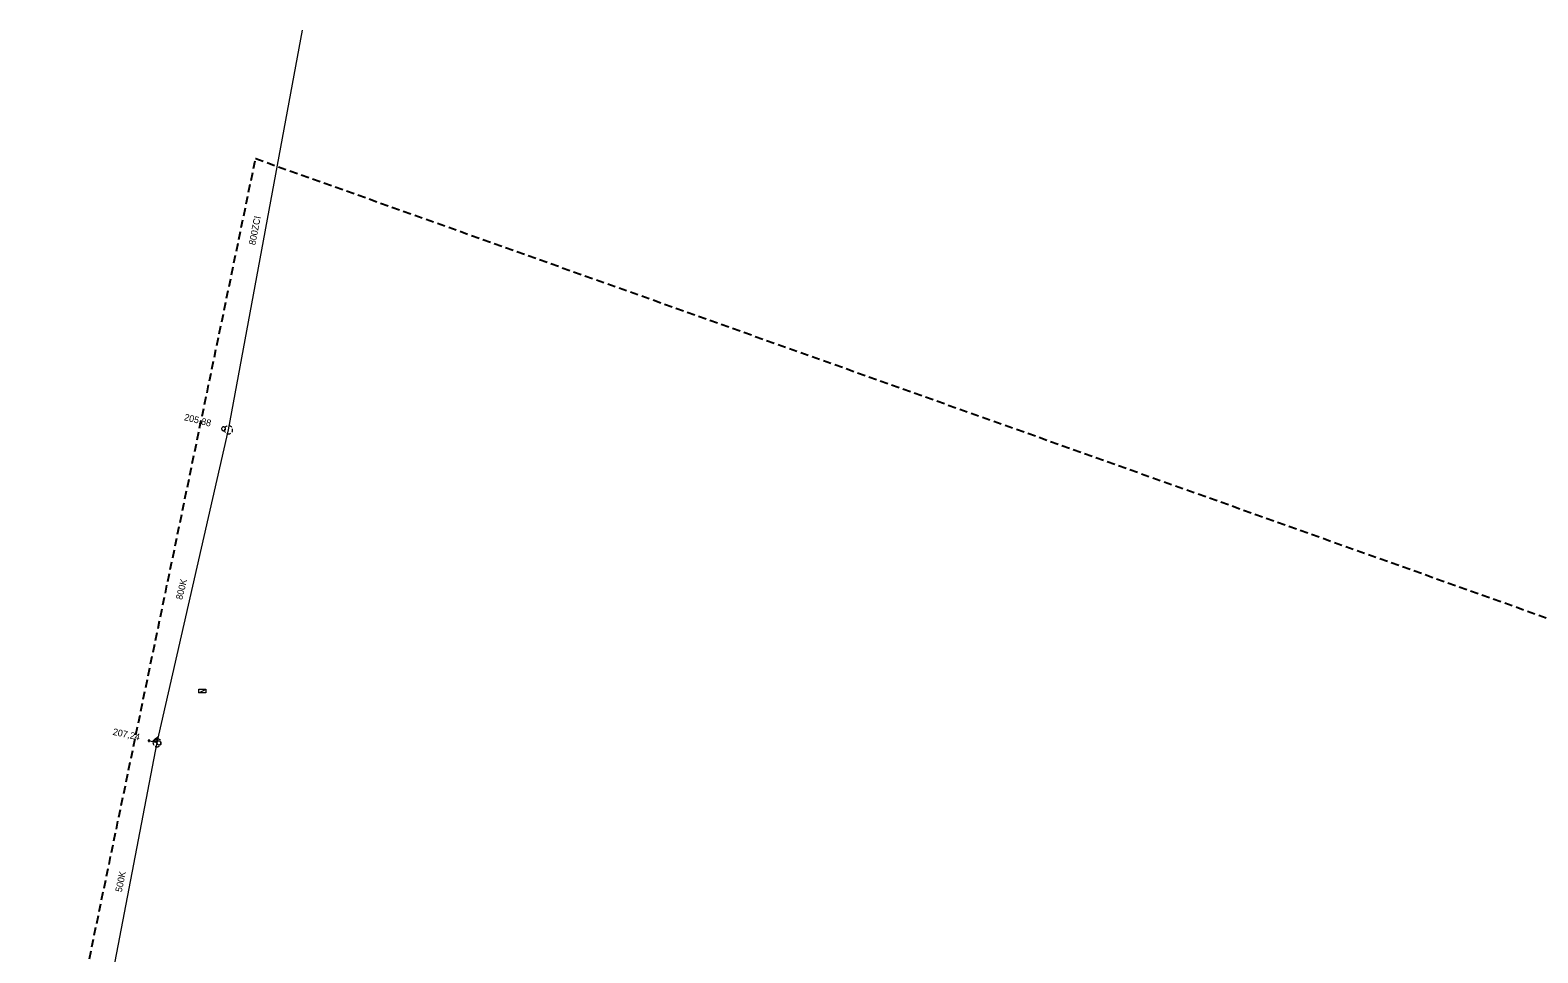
# Model space of a CAD drawing. Extents: x -739741 to -739027, y -1046215 to -1045797.
# Drawn here: x -739738.4 to -739558.3, y -1045907.7 to -1045797.3 of the extents above; entities that cross this region are included whole.
import ezdxf

# ---------------------------------------------------------------- set-up
doc = ezdxf.new("R2010")
doc.units = 0
doc.header["$LTSCALE"] = 0.32
doc.linetypes.add('MEDIUM_DASHED', pattern=[4.5, 3, -1.5])
doc.layers.add('1', color=7, linetype='Continuous')
for name, color, linetype, lineweight in [('18', 7, 'Continuous', 13), ('20', 7, 'Continuous', 13), ('63', 7, 'MEDIUM_DASHED', 25)]:
    doc.layers.add(name, color=color, linetype=linetype, lineweight=lineweight)

msp = doc.modelspace()

# ---------------------------------------------------------------- linework, layer by layer
at = {"layer": '18'}
msp.add_line((-739718.258, -1045876.558), (-739717.384, -1045876.146), dxfattribs=at)
for points in [[(-739715.058, -1045845.009), (-739715.064, -1045844.957), (-739715.081, -1045844.907), (-739715.11, -1045844.863), (-739715.148, -1045844.826), (-739715.193, -1045844.799), (-739715.243, -1045844.783), (-739715.295, -1045844.778), (-739715.347, -1045844.785), (-739715.396, -1045844.804), (-739715.44, -1045844.834), (-739715.475, -1045844.873), (-739715.501, -1045844.918), (-739715.516, -1045844.969), (-739715.519, -1045845.021), (-739715.511, -1045845.073), (-739715.49, -1045845.121), (-739715.46, -1045845.164), (-739715.42, -1045845.199), (-739715.374, -1045845.223), (-739715.323, -1045845.237), (-739715.271, -1045845.239), (-739715.219, -1045845.229), (-739715.171, -1045845.207), (-739715.129, -1045845.175), (-739715.096, -1045845.135), (-739715.072, -1045845.088), (-739715.059, -1045845.037)], [(-739718.262, -1045876.146), (-739717.388, -1045876.146), (-739717.388, -1045876.558), (-739718.262, -1045876.558)], [(-739724.175, -1045882.212), (-739724.208, -1045882.211), (-739724.24, -1045882.221), (-739724.266, -1045882.241), (-739724.283, -1045882.27), (-739724.29, -1045882.303), (-739724.284, -1045882.336), (-739724.267, -1045882.365), (-739724.241, -1045882.387), (-739724.21, -1045882.398), (-739724.176, -1045882.396), (-739724.145, -1045882.384), (-739724.121, -1045882.362), (-739724.105, -1045882.331), (-739724.101, -1045882.299), (-739724.109, -1045882.266), (-739724.128, -1045882.238), (-739724.156, -1045882.218)], [(-739724.179, -1045882.239), (-739724.207, -1045882.238), (-739724.233, -1045882.25), (-739724.252, -1045882.27), (-739724.261, -1045882.298), (-739724.258, -1045882.325), (-739724.244, -1045882.35), (-739724.221, -1045882.367), (-739724.193, -1045882.372), (-739724.165, -1045882.365), (-739724.143, -1045882.348), (-739724.129, -1045882.323), (-739724.127, -1045882.296), (-739724.137, -1045882.269), (-739724.157, -1045882.248)], [(-739722.789, -1045882.569), (-739722.795, -1045882.517), (-739722.813, -1045882.467), (-739722.841, -1045882.423), (-739722.879, -1045882.386), (-739722.924, -1045882.359), (-739722.974, -1045882.343), (-739723.026, -1045882.338), (-739723.078, -1045882.345), (-739723.127, -1045882.364), (-739723.171, -1045882.394), (-739723.206, -1045882.433), (-739723.232, -1045882.478), (-739723.247, -1045882.529), (-739723.25, -1045882.581), (-739723.242, -1045882.633), (-739723.221, -1045882.681), (-739723.191, -1045882.724), (-739723.151, -1045882.759), (-739723.105, -1045882.783), (-739723.054, -1045882.797), (-739723.002, -1045882.799), (-739722.95, -1045882.789), (-739722.902, -1045882.767), (-739722.86, -1045882.735), (-739722.827, -1045882.695), (-739722.803, -1045882.648), (-739722.791, -1045882.597)]]:
    msp.add_lwpolyline(points, close=True, dxfattribs=at)
for points in [[(-739715.188, -1045845.049), (-739715.193, -1045845.126), (-739715.188, -1045845.203), (-739715.171, -1045845.278), (-739715.142, -1045845.349), (-739715.102, -1045845.415), (-739715.087, -1045845.437)], [(-739714.843, -1045844.657), (-739714.914, -1045844.685), (-739714.98, -1045844.724), (-739715.041, -1045844.772), (-739715.092, -1045844.829), (-739715.115, -1045844.863)], [(-739714.301, -1045844.84), (-739714.352, -1045844.782), (-739714.409, -1045844.732), (-739714.475, -1045844.691), (-739714.546, -1045844.662), (-739714.595, -1045844.648)], [(-739714.306, -1045845.426), (-739714.266, -1045845.361), (-739714.235, -1045845.291), (-739714.215, -1045845.216), (-739714.208, -1045845.14), (-739714.213, -1045845.063), (-739714.218, -1045845.028)], [(-739714.929, -1045845.566), (-739714.86, -1045845.597), (-739714.784, -1045845.616), (-739714.708, -1045845.623), (-739714.632, -1045845.618), (-739714.556, -1045845.601), (-739714.485, -1045845.573), (-739714.424, -1045845.538)], [(-739724.287, -1045882.284), (-739723.22, -1045882.527), (-739723.048, -1045881.775), (-739723.783, -1045882.399)], [(-739723.717, -1045882.459), (-739723.723, -1045882.536), (-739723.718, -1045882.613), (-739723.701, -1045882.688), (-739723.672, -1045882.759), (-739723.632, -1045882.825), (-739723.616, -1045882.847)], [(-739723.656, -1045882.375), (-739723.25, -1045882.468), (-739723.124, -1045881.916), (-739723.658, -1045882.375)], [(-739723.372, -1045882.067), (-739723.443, -1045882.095), (-739723.51, -1045882.134), (-739723.57, -1045882.182), (-739723.621, -1045882.239), (-739723.645, -1045882.273)], [(-739723.565, -1045882.348), (-739723.28, -1045882.413), (-739723.197, -1045882.051), (-739723.565, -1045882.349)], [(-739723.459, -1045882.976), (-739723.389, -1045883.007), (-739723.314, -1045883.026), (-739723.238, -1045883.033), (-739723.161, -1045883.028), (-739723.086, -1045883.011), (-739723.014, -1045882.983), (-739722.954, -1045882.948)], [(-739722.831, -1045882.25), (-739722.881, -1045882.192), (-739722.939, -1045882.142), (-739723.004, -1045882.101), (-739723.075, -1045882.072), (-739723.124, -1045882.058)], [(-739722.836, -1045882.836), (-739722.795, -1045882.771), (-739722.764, -1045882.701), (-739722.745, -1045882.626), (-739722.737, -1045882.55), (-739722.742, -1045882.473), (-739722.748, -1045882.438)]]:
    msp.add_lwpolyline(points, dxfattribs=at)
at = {"layer": '20'}
msp.add_line((-739714.69, -1045845.12), (-739705.87, -1045797.35), dxfattribs=at)
msp.add_line((-739714.69, -1045845.12), (-739705.87, -1045797.35), dxfattribs=at)
msp.add_lwpolyline([(-739719.059, -1045916.96), (-739729.359, -1045914.5), (-739723.219, -1045882.53), (-739714.69, -1045845.12)], dxfattribs=at)
msp.add_lwpolyline([(-739719.059, -1045916.96), (-739729.359, -1045914.5), (-739723.219, -1045882.53), (-739714.69, -1045845.12)], dxfattribs=at)
at = {"layer": '63'}
msp.add_lwpolyline([(-739088.915, -1046214.93), (-739738.392, -1045952.844), (-739738.394, -1045952.843), (-739738.395, -1045952.842), (-739738.397, -1045952.841), (-739738.398, -1045952.839), (-739738.398, -1045952.837), (-739738.398, -1045952.835), (-739738.398, -1045952.833), (-739734.244, -1045922.471), (-739734.244, -1045922.47), (-739711.46, -1045812.716), (-739711.459, -1045812.714), (-739711.458, -1045812.713), (-739711.457, -1045812.711), (-739711.456, -1045812.71), (-739711.454, -1045812.709), (-739711.452, -1045812.709), (-739711.45, -1045812.708), (-739711.448, -1045812.708), (-739711.447, -1045812.709), (-739026.908, -1046056.391)], dxfattribs=at)

# ---------------------------------------------------------------- texts
at = {"layer": '1'}
for s, rotation, p in [('800ZCI', 79, (-739711.505, -1045823.101)), ('205,88', 346, (-739720.056, -1045843.967)), ('800K', 76, (-739720.24, -1045865.503)), ('207,24', 348, (-739728.582, -1045881.592)), ('500K', 78, (-739727.462, -1045900.452))]:
    msp.add_text(s, height=0.8, rotation=rotation, dxfattribs=at).set_placement(p)

doc.saveas('drawing.dxf')
